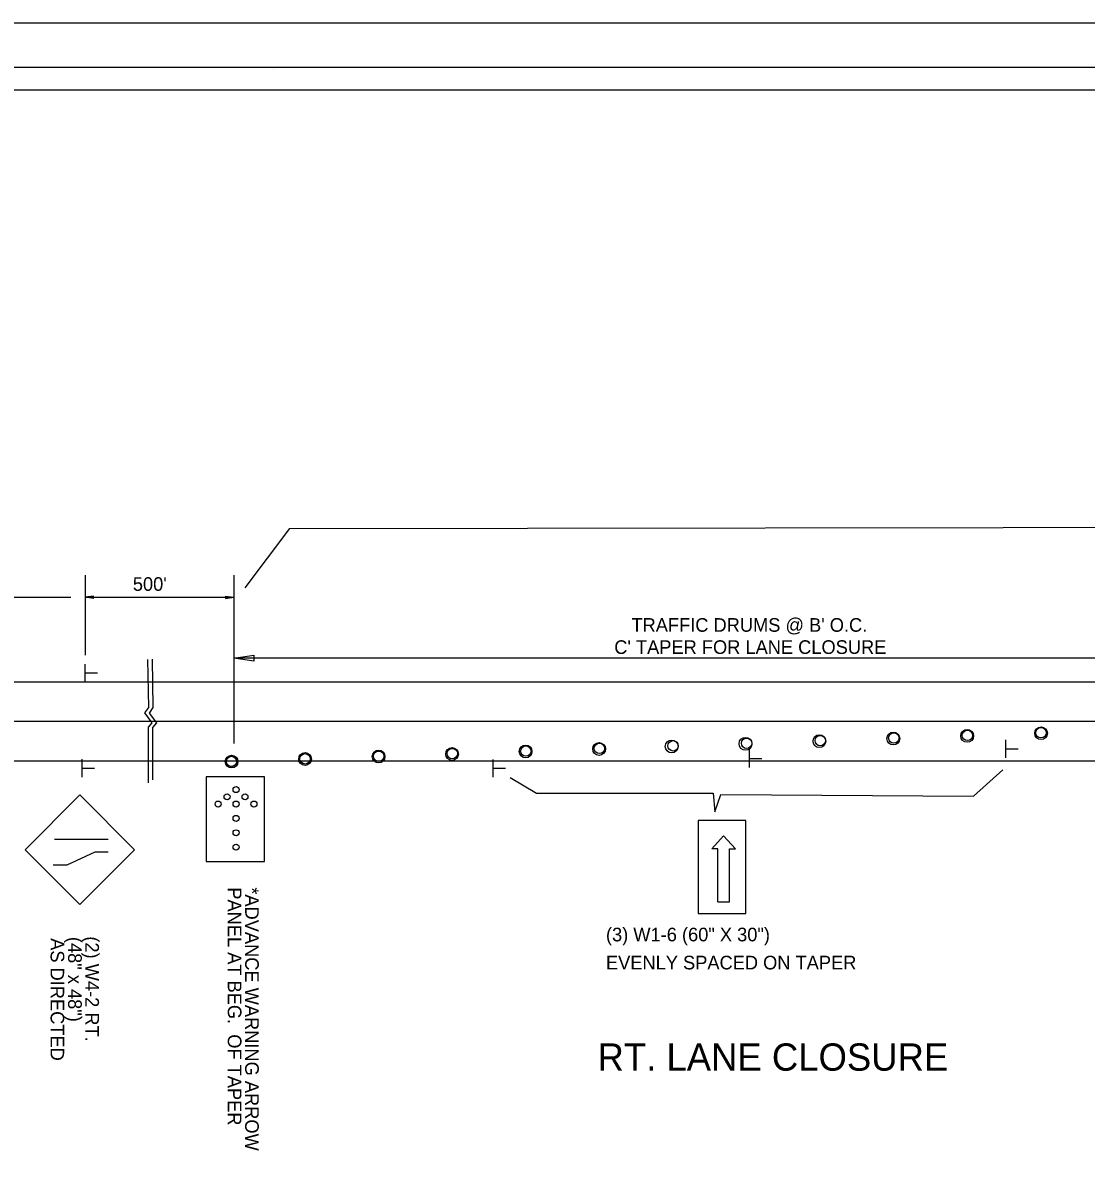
# Model space of a CAD drawing. Extents: x -500 to 213, y 382723 to 382830.
# Drawn here: x -244.84 to -198.06, y 382779.8 to 382829.8 of the extents above; entities that cross this region are included whole.
import ezdxf

# ---------------------------------------------------------------- set-up
doc = ezdxf.new("R2010")
doc.units = 0
for name, color, linetype in [('Default', 7, 'Continuous'), ('R_Border', 7, 'Continuous'), ('R_No Plot', 7, 'Continuous')]:
    doc.layers.add(name, color=color, linetype=linetype)

msp = doc.modelspace()

# ---------------------------------------------------------------- linework, layer by layer
at = {"layer": 'Default'}
for p, q in [((-242.093, 382805.499), (-242.093, 382801.978)), ((-235.546, 382805.499), (-235.546, 382798.085)), ((-247.944, 382804.52), (-242.726, 382804.52)), ((-241.718, 382804.576), (-242.093, 382804.52)), ((-242.093, 382804.52), (-235.546, 382804.52)), ((-241.718, 382804.464), (-242.093, 382804.52)), ((-241.718, 382804.567), (-242.03, 382804.52)), ((-241.718, 382804.473), (-242.03, 382804.52)), ((-241.718, 382804.557), (-241.966, 382804.52)), ((-241.718, 382804.482), (-241.966, 382804.52)), ((-241.718, 382804.548), (-241.904, 382804.52)), ((-241.718, 382804.492), (-241.904, 382804.52)), ((-241.718, 382804.538), (-241.84, 382804.52)), ((-241.718, 382804.502), (-241.84, 382804.52)), ((-241.718, 382804.529), (-241.777, 382804.52)), ((-241.718, 382804.511), (-241.777, 382804.52)), ((-241.718, 382804.464), (-241.718, 382804.576)), ((-235.921, 382804.576), (-235.546, 382804.52)), ((-235.921, 382804.576), (-235.921, 382804.464)), ((-235.921, 382804.567), (-235.608, 382804.52)), ((-235.921, 382804.557), (-235.673, 382804.52)), ((-235.921, 382804.548), (-235.735, 382804.52)), ((-235.921, 382804.538), (-235.799, 382804.52)), ((-235.921, 382804.529), (-235.862, 382804.52)), ((-235.921, 382804.464), (-235.546, 382804.52)), ((-235.921, 382804.501), (-235.799, 382804.52)), ((-235.921, 382804.482), (-235.673, 382804.52)), ((-235.921, 382804.473), (-235.608, 382804.52)), ((-235.921, 382804.492), (-235.735, 382804.52)), ((-235.921, 382804.511), (-235.862, 382804.52)), ((-235.546, 382803.216), (-235.546, 382799.695)), ((-235.546, 382801.848), (-234.677, 382801.979)), ((-234.677, 382801.979), (-234.677, 382801.718)), ((-242.093, 382800.804), (-242.093, 382801.586)), ((-190.345, 382801.848), (-235.546, 382801.848)), ((-234.677, 382801.718), (-235.546, 382801.848)), ((-242.082, 382801.193), (-241.548, 382801.193)), ((-251.538, 382800.808), (-235.546, 382800.808)), ((-235.546, 382800.808), (-164.267, 382800.808)), ((-251.538, 382799.07), (-235.546, 382799.07)), ((-235.546, 382799.07), (-164.267, 382799.07)), ((-201.601, 382797.462), (-201.601, 382798.244)), ((-201.59, 382797.851), (-201.056, 382797.851)), ((-242.22, 382796.613), (-242.22, 382797.395)), ((-224.143, 382796.609), (-224.143, 382797.391)), ((-212.872, 382797.035), (-212.872, 382797.818)), ((-212.861, 382797.424), (-212.327, 382797.424)), ((-251.538, 382797.331), (-235.546, 382797.331)), ((-242.208, 382797.002), (-241.674, 382797.002)), ((-235.546, 382797.331), (-164.267, 382797.331)), ((-224.132, 382796.998), (-223.598, 382796.998)), ((-242.326, 382795.827), (-244.735, 382793.418)), ((-242.326, 382795.827), (-239.916, 382793.418)), ((-243.442, 382793.881), (-241.072, 382793.881)), ((-214.526, 382793.461), (-214.007, 382794.03)), ((-214.007, 382794.03), (-213.488, 382793.461)), ((-244.735, 382793.418), (-242.326, 382791.008)), ((-239.916, 382793.418), (-242.326, 382791.008)), ((-214.266, 382793.461), (-214.526, 382793.461)), ((-214.266, 382791.13), (-214.266, 382793.461)), ((-213.747, 382791.13), (-213.747, 382793.461)), ((-213.747, 382793.461), (-213.488, 382793.461)), ((-242.88, 382792.757), (-241.655, 382793.319)), ((-241.655, 382793.319), (-241.072, 382793.319)), ((-243.493, 382792.757), (-242.88, 382792.757)), ((-214.266, 382791.13), (-213.747, 382791.13))]:
    msp.add_line(p, q, dxfattribs=at)
for points in [[(-235.059, 382804.933), (-233.084, 382807.551), (-191.258, 382807.599), (-190.452, 382810.018), (-190.38, 382807.634), (-165.711, 382807.3), (-164.57, 382804.702)], [(-239.343, 382801.779), (-239.311, 382799.675), (-239.473, 382799.434), (-239.157, 382799.001), (-239.323, 382798.801), (-239.324, 382796.355)], [(-239.143, 382801.798), (-239.111, 382799.667), (-239.273, 382799.425), (-238.957, 382798.992), (-239.124, 382798.793), (-239.124, 382796.496)], [(-223.391, 382796.588), (-222.233, 382795.906), (-214.467, 382795.906), (-214.399, 382795.088), (-214.127, 382795.838), (-203.024, 382795.77), (-201.729, 382796.929)]]:
    msp.add_lwpolyline(points, dxfattribs=at)
for points in [[(-236.771, 382796.617), (-236.771, 382792.893), (-234.195, 382792.893), (-234.195, 382796.617)], [(-215.12, 382794.696), (-215.12, 382790.609), (-213.03, 382790.609), (-213.03, 382794.696)]]:
    msp.add_lwpolyline(points, close=True, dxfattribs=at)
for centre, radius in [((-213.045, 382798.075), 0.281), ((-209.795, 382798.191), 0.281), ((-209.759, 382798.216), 0.229), ((-206.545, 382798.308), 0.281), ((-206.522, 382798.331), 0.229), ((-203.295, 382798.424), 0.281), ((-203.285, 382798.445), 0.229), ((-200.045, 382798.541), 0.281), ((-200.048, 382798.56), 0.229), ((-225.951, 382797.627), 0.281), ((-225.943, 382797.643), 0.229), ((-222.718, 382797.738), 0.281), ((-222.706, 382797.757), 0.229), ((-219.484, 382797.849), 0.281), ((-219.469, 382797.872), 0.229), ((-216.295, 382797.959), 0.281), ((-216.232, 382797.987), 0.229), ((-212.996, 382798.101), 0.229), ((-235.651, 382797.294), 0.281), ((-235.665, 382797.299), 0.229), ((-235.653, 382797.298), 0.229), ((-232.418, 382797.405), 0.281), ((-232.416, 382797.413), 0.229), ((-229.184, 382797.516), 0.281), ((-229.18, 382797.528), 0.229), ((-235.849, 382795.743), 0.131), ((-235.454, 382796.059), 0.131), ((-235.059, 382795.743), 0.131), ((-236.243, 382795.426), 0.131), ((-235.454, 382795.426), 0.131), ((-234.665, 382795.426), 0.131), ((-235.454, 382794.794), 0.131), ((-235.454, 382794.162), 0.131), ((-235.454, 382793.529), 0.131)]:
    msp.add_circle(centre, radius, dxfattribs=at)
at = {"layer": 'R_Border'}
for p, q in [((-310.08, 382827.85), (-151.99, 382827.85)), ((-233.82, 382827.72), (-233.82, 382827.72)), ((-233.82, 382827.72), (-233.82, 382827.72))]:
    msp.add_line(p, q, dxfattribs=at)
at = {"layer": 'R_No Plot'}
for points in [[(-316.283, 382829.798), (-149.613, 382829.798), (-149.613, 382723.129), (-316.283, 382723.129)], [(-152.99, 382777.485), (-309.08, 382777.485), (-309.08, 382826.85), (-184.31, 382826.85), (-184.31, 382821.91), (-175.54, 382821.91), (-163.49, 382821.91), (-163.49, 382810.744), (-152.99, 382810.744)], [(-309.08, 382826.85), (-184.31, 382826.85), (-184.31, 382821.91), (-175.54, 382821.91), (-163.49, 382821.91), (-163.49, 382810.744), (-152.99, 382810.744), (-152.99, 382726.12), (-309.08, 382726.12)]]:
    msp.add_lwpolyline(points, close=True, dxfattribs=at)

# ---------------------------------------------------------------- texts
at = {"layer": 'Default'}
for s, height, p in [("500'", 0.6, (-239.993, 382804.805)), ("TRAFFIC DRUMS @ B' O.C.", 0.6, (-218.062, 382803.004)), ("C' TAPER FOR LANE CLOSURE", 0.6, (-218.818, 382802.03)), ('RT. LANE CLOSURE', 1.2, (-219.553, 382783.695))]:
    msp.add_text(s, height=height, dxfattribs=at).set_placement(p)
for s, rotation, p in [('PANEL AT BEG.  OF TAPER', 270, (-235.817, 382791.762)), ('*ADVANCE WARNING ARROW', 270, (-235.053, 382791.762)), ('(3) W1-6 (60" X 30")', 0.0075, (-219.183, 382789.385)), ('AS DIRECTED ', 270, (-243.612, 382789.524)), ('(48" x 48")', 270, (-242.84, 382789.58)), ('(2) W4-2 RT.', 270, (-242.082, 382789.605)), ('EVENLY SPACED ON TAPER', 0.0075, (-219.182, 382788.15))]:
    msp.add_text(s, height=0.6, rotation=rotation, dxfattribs=at).set_placement(p)

doc.saveas('drawing.dxf')
